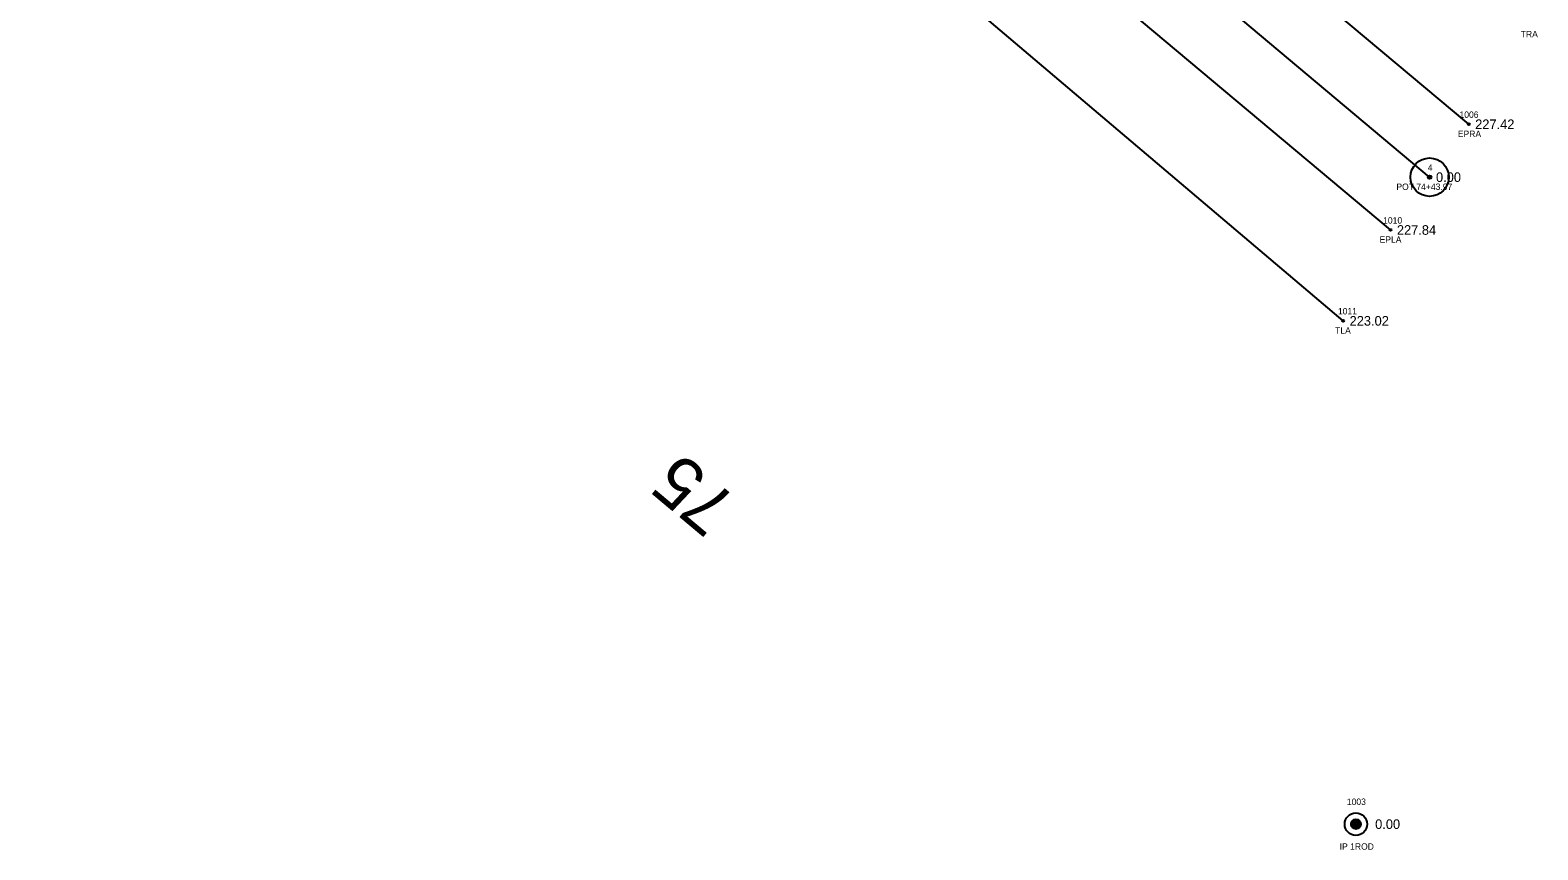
# Model space of a CAD drawing. Extents: x 2259948 to 2261336, y 1064647 to 1065986.
# Drawn here: x 2260900.1 to 2261135.7, y 1064714.1 to 1064842.1 of the extents above; entities that cross this region are included whole.
import ezdxf

# ---------------------------------------------------------------- set-up
doc = ezdxf.new("R2010")
doc.units = 0
for name, color, linetype in [('RD_EX_DV_Prop_txCode', 7, 'Continuous'), ('RD_EX_DV_PropPin', 7, 'Continuous'), ('RD_EX_Road', 7, 'Continuous'), ('RD_EX_Road_txCode', 7, 'Continuous'), ('RD_EX_TX_DV_Prop_ELEV', 7, 'Continuous'), ('RD_EX_TX_Road_ELEV', 7, 'Continuous'), ('RD_EX_TX_VEG_ELEV', 7, 'Continuous'), ('RD_EX_VEG', 7, 'Continuous'), ('RD_EX_VEG_txCode', 7, 'Continuous'), ('RD_HC_Cl', 7, 'Continuous'), ('RD_HC_Data', 7, 'Continuous'), ('RD_HC_Survey_ELEV', 7, 'Continuous'), ('RD_HC_TX_Sta50', 7, 'Continuous'), ('RD_HC_txCode', 7, 'Continuous'), ('RD_SMD_Locator', 7, 'Continuous')]:
    doc.layers.add(name, color=color, linetype=linetype)

msp = doc.modelspace()

# ---------------------------------------------------------------- linework, layer by layer
at = {"layer": 'RD_EX_DV_PropPin'}
for p, q in [((2261106.58, 1064717.77), (2261106.58, 1064718.37)), ((2261106.61, 1064717.7), (2261106.61, 1064718.44)), ((2261106.65, 1064717.64), (2261106.65, 1064718.5)), ((2261106.68, 1064717.6), (2261106.68, 1064718.55)), ((2261106.72, 1064717.56), (2261106.72, 1064718.59)), ((2261106.75, 1064717.52), (2261106.75, 1064718.62)), ((2261106.79, 1064717.49), (2261106.79, 1064718.65)), ((2261106.82, 1064717.46), (2261106.82, 1064718.68)), ((2261106.86, 1064717.44), (2261106.86, 1064718.71)), ((2261106.9, 1064717.41), (2261106.9, 1064718.73)), ((2261106.93, 1064717.4), (2261106.93, 1064718.75)), ((2261106.97, 1064717.38), (2261106.97, 1064718.76)), ((2261107, 1064717.36), (2261107, 1064718.78)), ((2261107.04, 1064717.35), (2261107.04, 1064718.79)), ((2261107.07, 1064717.34), (2261107.07, 1064718.8)), ((2261107.11, 1064717.33), (2261107.11, 1064718.81)), ((2261107.14, 1064717.32), (2261107.14, 1064718.82)), ((2261107.18, 1064717.32), (2261107.18, 1064718.82)), ((2261107.21, 1064717.31), (2261107.21, 1064718.83)), ((2261107.25, 1064717.31), (2261107.25, 1064718.83)), ((2261107.28, 1064717.31), (2261107.28, 1064718.83)), ((2261107.32, 1064717.31), (2261107.32, 1064718.83)), ((2261107.35, 1064717.31), (2261107.35, 1064718.83)), ((2261107.39, 1064717.32), (2261107.39, 1064718.82)), ((2261107.42, 1064717.32), (2261107.42, 1064718.82)), ((2261107.46, 1064717.33), (2261107.46, 1064718.81)), ((2261107.49, 1064717.34), (2261107.49, 1064718.8)), ((2261107.53, 1064717.35), (2261107.53, 1064718.79)), ((2261107.56, 1064717.36), (2261107.56, 1064718.78)), ((2261107.6, 1064717.38), (2261107.6, 1064718.76)), ((2261107.63, 1064717.4), (2261107.63, 1064718.75)), ((2261107.67, 1064717.41), (2261107.67, 1064718.73)), ((2261107.7, 1064717.44), (2261107.7, 1064718.71)), ((2261107.74, 1064717.46), (2261107.74, 1064718.68)), ((2261107.77, 1064717.49), (2261107.77, 1064718.65)), ((2261107.81, 1064717.52), (2261107.81, 1064718.62)), ((2261107.84, 1064717.56), (2261107.84, 1064718.59)), ((2261107.88, 1064717.6), (2261107.88, 1064718.55)), ((2261107.91, 1064717.64), (2261107.91, 1064718.5)), ((2261107.95, 1064717.7), (2261107.95, 1064718.44)), ((2261107.98, 1064717.77), (2261107.98, 1064718.37)), ((2261106.54, 1064717.88), (2261106.54, 1064718.27)), ((2261108.02, 1064717.88), (2261108.02, 1064718.27))]:
    msp.add_line(p, q, dxfattribs=at)
for radius in [1.75, 0.761]:
    msp.add_circle((2261107.28, 1064718.07), radius, dxfattribs=at)
at = {"layer": 'RD_EX_Road'}
for points in [[(2261124.91, 1064827.37), (2261072.16, 1064871.6), (2261053.72, 1064886.47), (2261045.58, 1064893.1), (2260972.89, 1064954.76), (2260940.74, 1064982.39), (2260933.33, 1064988.76), (2260898.06, 1065017.6), (2260832.89, 1065075.07)], [(2261112.68, 1064810.86), (2261032.95, 1064877.72), (2260956.01, 1064942.53), (2260884.53, 1065002.6), (2260818.6, 1065058.26)]]:
    msp.add_lwpolyline(points, dxfattribs=at)
at = {"layer": 'RD_EX_VEG'}
msp.add_lwpolyline([(2261105.29, 1064796.67), (2260883, 1064984.96), (2260766.14, 1065062.68), (2260367.33, 1065416.28), (2260257.33, 1065527.76)], dxfattribs=at)
at = {"layer": 'RD_HC_Cl'}
msp.add_line((2261118.79, 1064819.11), (2260589.55, 1065263.13), dxfattribs=at)
at = {"layer": 'RD_HC_Data'}
for radius in [3, 0.282]:
    msp.add_circle((2261118.79, 1064819.11), radius, dxfattribs=at)
at = {"layer": 'RD_SMD_Locator'}
for centre in [(2261124.91, 1064827.37), (2261118.79, 1064819.11), (2261112.68, 1064810.86), (2261105.29, 1064796.67), (2261107.28, 1064718.07)]:
    msp.add_circle(centre, 0.15, dxfattribs=at)

# ---------------------------------------------------------------- texts
at = {"layer": 'RD_EX_DV_Prop_txCode'}
for s, p in [('1003', (2261105.86, 1064721.07)), ('IP 1ROD', (2261104.74, 1064714.07))]:
    msp.add_text(s, height=1, dxfattribs=at).set_placement(p)
at = {"layer": 'RD_EX_Road_txCode'}
for s, p in [('1006', (2261123.46, 1064828.37)), ('EPRA', (2261123.2, 1064825.37)), ('1010', (2261111.53, 1064811.86)), ('EPLA', (2261110.98, 1064808.86))]:
    msp.add_text(s, height=1, dxfattribs=at).set_placement(p)
at = {"layer": 'RD_EX_TX_DV_Prop_ELEV'}
msp.add_text('0.00', height=1.5, dxfattribs=at).set_placement((2261110.28, 1064717.32))
at = {"layer": 'RD_EX_TX_Road_ELEV'}
for s, p in [('227.42', (2261125.91, 1064826.62)), ('227.84', (2261113.68, 1064810.11))]:
    msp.add_text(s, height=1.5, dxfattribs=at).set_placement(p)
at = {"layer": 'RD_EX_TX_VEG_ELEV'}
msp.add_text('223.02', height=1.5, dxfattribs=at).set_placement((2261106.29, 1064795.92))
at = {"layer": 'RD_EX_VEG_txCode'}
for s, p in [('TRA', (2261133.03, 1064840.95)), ('1011', (2261104.47, 1064797.67)), ('TLA', (2261104.03, 1064794.67))]:
    msp.add_text(s, height=1, dxfattribs=at).set_placement(p)
at = {"layer": 'RD_HC_Survey_ELEV'}
msp.add_text('0.00', height=1.5, dxfattribs=at).set_placement((2261119.79, 1064818.36))
at = {"layer": 'RD_HC_TX_Sta50'}
msp.add_text('75', height=8, rotation=140.0043, dxfattribs=at).set_placement((2261010.87, 1064768.68))
at = {"layer": 'RD_HC_txCode'}
for s, p in [('4', (2261118.51, 1064820.11)), ('POT 74+43.97', (2261113.6, 1064817.11))]:
    msp.add_text(s, height=1, dxfattribs=at).set_placement(p)

doc.saveas('drawing.dxf')
